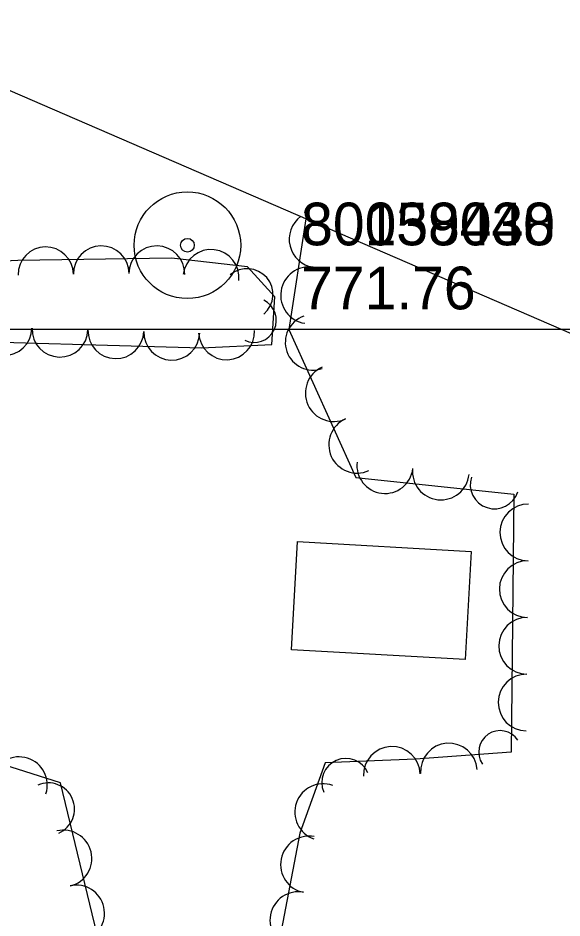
# Model space of a CAD drawing. Extents: x 591954 to 597000, y 198576 to 213500.
# Drawn here: x 596347.9 to 596424.4, y 204417.2 to 204543.7 of the extents above; entities that cross this region are included whole.
import ezdxf

# ---------------------------------------------------------------- set-up
doc = ezdxf.new("R2010")
doc.units = 0
for name, color, linetype in [('Level 10', 7, 'Continuous'), ('Level 12', 7, 'Continuous'), ('Level 18', 7, 'Continuous'), ('Level 4', 7, 'Continuous'), ('Level 6', 7, 'Continuous')]:
    doc.layers.add(name, color=color, linetype=linetype)

msp = doc.modelspace()

# ---------------------------------------------------------------- linework, layer by layer
at = {"layer": 'Level 10'}
for q in [(597000, 204500), (597000, 204500), (596500, 204500), (597000, 204500)]:
    msp.add_line((595000, 204500), q, dxfattribs=at)
at = {"layer": 'Level 12'}
msp.add_lwpolyline([(596386.35, 204454.88), (596387.2, 204470.1), (596411.62, 204468.74), (596410.78, 204453.52), (596386.35, 204454.88)], dxfattribs=at)
msp.add_lwpolyline([(596386.35, 204454.88), (596387.2, 204470.1), (596411.62, 204468.74), (596410.78, 204453.52), (596386.35, 204454.88)], dxfattribs=at)
msp.add_lwpolyline([(596386.35, 204454.88), (596387.2, 204470.1), (596411.62, 204468.74), (596410.78, 204453.52), (596386.35, 204454.88)], dxfattribs=at)
at = {"layer": 'Level 18'}
for points in [[(596388.37, 204515.51), (596385.98, 204499.94), (596395.39, 204479.12), (596417.64, 204476.8), (596417.27, 204440.5), (596403.82, 204439.52), (596391.08, 204439.01), (596387.54, 204429.12), (596382.51, 204402.87), (596373.57, 204389.44), (596366.52, 204390.08), (596359.8, 204381.14), (596360.59, 204369.44), (596367.74, 204350.45), (596362.18, 204329.55), (596359.68, 204307.74), (596362.89, 204288.9), (596380.98, 204284.12), (596403.34, 204276.53), (596404.62, 204254.71), (596401.31, 204211.06), (596400.51, 204187.91)], [(596388.37, 204515.51), (596385.98, 204499.94), (596395.39, 204479.12), (596417.64, 204476.8), (596417.27, 204440.5), (596403.82, 204439.52), (596391.08, 204439.01), (596387.54, 204429.12), (596382.51, 204402.87), (596373.57, 204389.44), (596366.52, 204390.08), (596359.8, 204381.14), (596360.59, 204369.44), (596367.74, 204350.45), (596362.18, 204329.55), (596359.68, 204307.74), (596362.89, 204288.9), (596380.98, 204284.12), (596403.34, 204276.53), (596404.62, 204254.71), (596401.31, 204211.06), (596400.51, 204187.91)], [(596388.37, 204515.51), (596385.98, 204499.94), (596395.39, 204479.12), (596417.64, 204476.8), (596417.27, 204440.5), (596403.82, 204439.52), (596391.08, 204439.01), (596387.54, 204429.12), (596382.51, 204402.87), (596373.57, 204389.44), (596366.52, 204390.08), (596359.8, 204381.14), (596360.59, 204369.44), (596367.74, 204350.45), (596362.18, 204329.55), (596359.68, 204307.74), (596362.89, 204288.9), (596380.98, 204284.12), (596403.34, 204276.53), (596404.62, 204254.71), (596401.31, 204211.06), (596400.51, 204187.91)], [(596347.87, 204509.63), (596335.67, 204509.04), (596312.32, 204509.11), (596278.99, 204509.61), (596240.45, 204510.86), (596231.4, 204510.68), (596228.72, 204506.55), (596235.99, 204501.8), (596265.67, 204500.97), (596297.37, 204499.34), (596334.05, 204498.49), (596373.71, 204497.37), (596383.61, 204497.84), (596384, 204504.52), (596380.18, 204508.74), (596369.46, 204509.95), (596347.87, 204509.63)], [(596347.87, 204509.63), (596335.67, 204509.04), (596312.32, 204509.11), (596278.99, 204509.61), (596240.45, 204510.86), (596231.4, 204510.68), (596228.72, 204506.55), (596235.99, 204501.8), (596265.67, 204500.97), (596297.37, 204499.34), (596334.05, 204498.49), (596373.71, 204497.37), (596383.61, 204497.84), (596384, 204504.52), (596380.18, 204508.74), (596369.46, 204509.95), (596347.87, 204509.63)], [(596347.87, 204509.63), (596335.67, 204509.04), (596312.32, 204509.11), (596278.99, 204509.61), (596240.45, 204510.86), (596231.4, 204510.68), (596228.72, 204506.55), (596235.99, 204501.8), (596265.67, 204500.97), (596297.37, 204499.34), (596334.05, 204498.49), (596373.71, 204497.37), (596383.61, 204497.84), (596384, 204504.52), (596380.18, 204508.74), (596369.46, 204509.95), (596347.87, 204509.63)], [(596359.02, 204414.84), (596353.88, 204436.19), (596338.91, 204440.93), (596330.87, 204435.24), (596328.94, 204424.36), (596321.95, 204423.07), (596296.06, 204431), (596272.59, 204442.48)], [(596359.02, 204414.84), (596353.88, 204436.19), (596338.91, 204440.93), (596330.87, 204435.24), (596328.94, 204424.36), (596321.95, 204423.07), (596296.06, 204431), (596272.59, 204442.48)], [(596359.02, 204414.84), (596353.88, 204436.19), (596338.91, 204440.93), (596330.87, 204435.24), (596328.94, 204424.36), (596321.95, 204423.07), (596296.06, 204431), (596272.59, 204442.48)]]:
    msp.add_lwpolyline(points, dxfattribs=at)
for centre, radius, start, end in [((596390.03, 204512.62), 3.99, 126.6594, 261.2888), ((596390.03, 204512.62), 3.99, 126.6594, 261.2888), ((596390.03, 204512.62), 3.99, 126.6594, 261.2888), ((596351.79, 204507.65), 3.89, 0.8694, 180.854), ((596351.79, 204507.65), 3.89, 0.8694, 180.854), ((596351.79, 204507.65), 3.89, 0.8694, 180.854), ((596359.61, 204507.75), 3.93, 0.8743, 180.859), ((596359.61, 204507.75), 3.93, 0.8743, 180.859), ((596359.61, 204507.75), 3.93, 0.8743, 180.859), ((596367.41, 204507.75), 3.93, 359.0741, 179.0588), ((596367.41, 204507.75), 3.93, 359.0741, 179.0588), ((596367.41, 204507.75), 3.93, 359.0741, 179.0588), ((596375.05, 204507.25), 3.93, 353.542, 173.5267), ((596375.05, 204507.25), 3.93, 353.542, 173.5267), ((596375.05, 204507.25), 3.93, 353.542, 173.5267), ((596380.12, 204504.86), 3.63, 310.7004, 130.6851), ((596380.12, 204504.86), 3.63, 310.7004, 130.6851), ((596380.12, 204504.86), 3.63, 310.7004, 130.6851), ((596388.83, 204504.75), 3.99, 81.3052, 261.2899), ((596388.83, 204504.75), 3.99, 81.3052, 261.2899), ((596388.83, 204504.75), 3.99, 81.3052, 261.2899), ((596381.12, 204501.23), 3.11, 244.5142, 64.4989), ((596381.12, 204501.23), 3.11, 244.5142, 64.4989), ((596381.12, 204501.23), 3.11, 244.5142, 64.4989), ((596389.39, 204498.13), 3.9, 109.5361, 289.5207), ((596389.39, 204498.13), 3.9, 109.5361, 289.5207), ((596389.39, 204498.13), 3.9, 109.5361, 289.5207), ((596345.93, 204500.21), 3.93, 178.3836, 358.3682), ((596345.93, 204500.21), 3.93, 178.3836, 358.3682), ((596345.93, 204500.21), 3.93, 178.3836, 358.3682), ((596353.79, 204499.99), 3.93, 178.3836, 358.3682), ((596353.79, 204499.99), 3.93, 178.3836, 358.3682), ((596353.79, 204499.99), 3.93, 178.3836, 358.3682), ((596361.66, 204499.77), 3.93, 178.3908, 358.3755), ((596361.66, 204499.77), 3.93, 178.3908, 358.3755), ((596361.66, 204499.77), 3.93, 178.3908, 358.3755), ((596369.52, 204499.55), 3.93, 178.3834, 358.368), ((596369.52, 204499.55), 3.93, 178.3834, 358.368), ((596369.52, 204499.55), 3.93, 178.3834, 358.368), ((596377.23, 204499.61), 3.93, 182.5719, 2.5565), ((596377.23, 204499.61), 3.93, 182.5719, 2.5565), ((596377.23, 204499.61), 3.93, 182.5719, 2.5565), ((596392.31, 204490.99), 3.99, 114.3249, 294.3096), ((596392.31, 204490.99), 3.99, 114.3249, 294.3096), ((596392.31, 204490.99), 3.99, 114.3249, 294.3096), ((596395.6, 204483.73), 3.99, 114.3314, 294.3161), ((596395.6, 204483.73), 3.99, 114.3314, 294.3161), ((596395.6, 204483.73), 3.99, 114.3314, 294.3161), ((596399.51, 204480.83), 3.95, 173.2449, 353.2296), ((596399.51, 204480.83), 3.95, 173.2449, 353.2296), ((596399.51, 204480.83), 3.95, 173.2449, 353.2296), ((596407.37, 204479.97), 3.99, 174.0668, 354.0514), ((596407.37, 204479.97), 3.99, 174.0668, 354.0514), ((596407.37, 204479.97), 3.99, 174.0668, 354.0514), ((596414.92, 204478.14), 3.42, 162.1982, 342.1829), ((596414.92, 204478.14), 3.42, 162.1982, 342.1829), ((596414.92, 204478.14), 3.42, 162.1982, 342.1829), ((596419.67, 204471.39), 3.99, 89.4254, 269.4101), ((596419.67, 204471.39), 3.99, 89.4254, 269.4101), ((596419.67, 204471.39), 3.99, 89.4254, 269.4101), ((596419.59, 204463.42), 3.99, 89.4326, 269.4173), ((596419.59, 204463.42), 3.99, 89.4326, 269.4173), ((596419.59, 204463.42), 3.99, 89.4326, 269.4173), ((596419.51, 204455.45), 3.99, 89.4326, 269.4172), ((596419.51, 204455.45), 3.99, 89.4326, 269.4172), ((596419.51, 204455.45), 3.99, 89.4326, 269.4172), ((596419.43, 204447.48), 3.99, 89.4254, 269.4101), ((596419.43, 204447.48), 3.99, 89.4254, 269.4101), ((596419.43, 204447.48), 3.99, 89.4254, 269.4101), ((596415.7, 204440.52), 3.01, 34.1127, 214.0974), ((596415.7, 204440.52), 3.01, 34.1127, 214.0974), ((596415.7, 204440.52), 3.01, 34.1127, 214.0974), ((596400.48, 204437.3), 3.99, 2.4382, 182.4229), ((596400.48, 204437.3), 3.99, 2.4382, 182.4229), ((596400.48, 204437.3), 3.99, 2.4382, 182.4229), ((596408.5, 204437.77), 3.99, 4.2024, 184.187), ((596408.5, 204437.77), 3.99, 4.2024, 184.187), ((596408.5, 204437.77), 3.99, 4.2024, 184.187), ((596348.03, 204435.86), 3.98, 342.4333, 162.418), ((596348.03, 204435.86), 3.98, 342.4333, 162.418), ((596348.03, 204435.86), 3.98, 342.4333, 162.418), ((596394.01, 204436.24), 3.39, 23.4338, 203.4184), ((596394.01, 204436.24), 3.39, 23.4338, 203.4184), ((596394.01, 204436.24), 3.39, 23.4338, 203.4184), ((596352.16, 204432.5), 3.68, 293.5799, 113.5646), ((596352.16, 204432.5), 3.68, 293.5799, 113.5646), ((596352.16, 204432.5), 3.68, 293.5799, 113.5646), ((596390.82, 204432.07), 3.99, 70.4336, 250.4183), ((596390.82, 204432.07), 3.99, 70.4336, 250.4183), ((596390.82, 204432.07), 3.99, 70.4336, 250.4183), ((596354.3, 204425.55), 3.98, 283.5462, 103.5309), ((596354.3, 204425.55), 3.98, 283.5462, 103.5309), ((596354.3, 204425.55), 3.98, 283.5462, 103.5309), ((596388.82, 204424.71), 3.99, 79.1447, 259.1294), ((596388.82, 204424.71), 3.99, 79.1447, 259.1294), ((596388.82, 204424.71), 3.99, 79.1447, 259.1294), ((596356.09, 204417.85), 3.97, 282.4848, 102.4694), ((596356.09, 204417.85), 3.97, 282.4848, 102.4694), ((596356.09, 204417.85), 3.97, 282.4848, 102.4694), ((596387.32, 204416.88), 3.99, 79.146, 259.1307), ((596387.32, 204416.88), 3.99, 79.146, 259.1307), ((596387.32, 204416.88), 3.99, 79.146, 259.1307)]:
    msp.add_arc(centre, radius, start, end, dxfattribs=at)
at = {"layer": 'Level 4'}
msp.add_lwpolyline([(596451.14, 204145.51), (596525.27, 204456.26), (596301.7, 204553.02), (596061.01, 204676.82), (595803.6, 204793.01), (595657.91, 204869.81), (595496.03, 204962.18), (595284.73, 205098.89)], dxfattribs=at)
msp.add_lwpolyline([(596451.14, 204145.51), (596525.27, 204456.26), (596301.7, 204553.02), (596061.01, 204676.82), (595803.6, 204793.01), (595657.91, 204869.81), (595496.03, 204962.18), (595284.73, 205098.89)], dxfattribs=at)
msp.add_lwpolyline([(596451.14, 204145.51), (596525.27, 204456.26), (596301.7, 204553.02), (596061.01, 204676.82), (595803.6, 204793.01), (595657.91, 204869.81), (595496.03, 204962.18), (595284.73, 205098.89)], dxfattribs=at)
at = {"layer": 'Level 6'}
for radius in [7.5, 7.5, 7.5, 7.5, 7.5, 7.5, 7.5, 7.5, 0.96, 0.96, 0.96, 0.96, 0.96, 0.96, 0.96, 0.96]:
    msp.add_circle((596371.72, 204511.78), radius, dxfattribs=at)

# ---------------------------------------------------------------- texts
for s, p in [('30058040', (596387.72, 204511.77)), ('30058040', (596387.72, 204511.77)), ('30058040', (596387.72, 204511.77)), ('30058040', (596387.72, 204511.77)), ('80139438', (596387.72, 204511.77)), ('80139438', (596387.72, 204511.77)), ('80139438', (596387.72, 204511.77)), ('80139438', (596387.72, 204511.77)), ('771.76', (596387.72, 204502.77)), ('771.76', (596387.72, 204502.77)), ('771.76', (596387.72, 204502.77)), ('771.76', (596387.72, 204502.77)), ('771.76', (596387.72, 204502.77)), ('771.76', (596387.72, 204502.77)), ('771.76', (596387.72, 204502.77)), ('771.76', (596387.72, 204502.77))]:
    msp.add_text(s, height=6, dxfattribs=at).set_placement(p)

doc.saveas('drawing.dxf')
